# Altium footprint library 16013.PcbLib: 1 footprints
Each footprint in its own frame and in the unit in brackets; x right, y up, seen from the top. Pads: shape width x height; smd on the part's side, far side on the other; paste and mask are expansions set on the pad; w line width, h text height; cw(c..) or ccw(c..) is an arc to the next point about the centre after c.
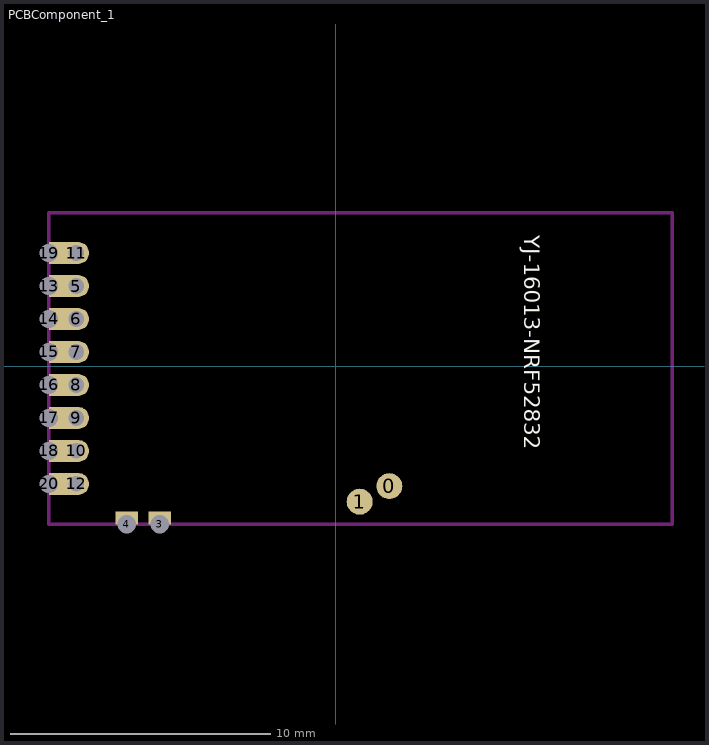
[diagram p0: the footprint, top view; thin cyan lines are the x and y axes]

## PCBComponent_1 [mm]
pads (20):
  round 1 smd: 0(2.067,-4.622) 1(0.927,-5.222)
  rect 0.85x0.5 hole 0.7 copper offset 0,0.25: 3(-6.773,-6.092) 4(-8.043,-6.092)
  oval 1x0.85 hole 0.6: 5(-9.993,3.083) 6(-9.993,1.813) 7(-9.993,0.543) 8(-9.993,-0.727) 9(-9.993,-1.997) 10(-9.993,-3.267) 11(-9.993,4.353) 12(-9.993,-4.537)
  rect 1x0.85 hole 0.7 copper offset 0.5,0: 13(-11.043,3.083) 14(-11.043,1.813) 15(-11.043,0.543) 16(-11.043,-0.727) 17(-11.043,-1.997) 18(-11.043,-3.267) 19(-11.043,4.353) 20(-11.043,-4.537)
Top Layer:
  lines w0.15: -10.503,0.637 cw(c-10.328,0.162) -9.97,0.52 ; -10.451,0.496 cw(c-10.238,-0.08) -9.804,0.354 ; -10.327,1.672 cw(c-9.985,1.33) -9.985,1.813 cw(c-9.985,2.296) -10.327,1.954 ; -10.327,2.942 cw(c-9.985,2.6) -9.985,3.083 cw(c-9.985,3.566) -10.327,3.224 ; -10.221,1.566 cw(c-9.623,0.968) -9.623,1.813 cw(c-9.623,2.658) -10.221,2.061
Bottom Layer:
  lines w0.3: -10.274,4.159 cw(c-9.804,3.689) -9.804,4.353 cw(c-9.804,5.017) -10.274,4.547 ; -10.23,4.216 cw(c-9.993,4.08) -9.993,4.353 cw(c-9.993,4.626) -10.23,4.49
Top Overlay:
  text "YJ-16013-NRF52832" at 7.267,5.038 h0.6
Keep-Out Layer:
  lines w0.127: -11.043,-6.092 -11.043,5.908 12.957,5.908 12.957,-6.092 -11.043,-6.092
